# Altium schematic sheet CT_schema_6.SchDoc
size 368 x 245 mm
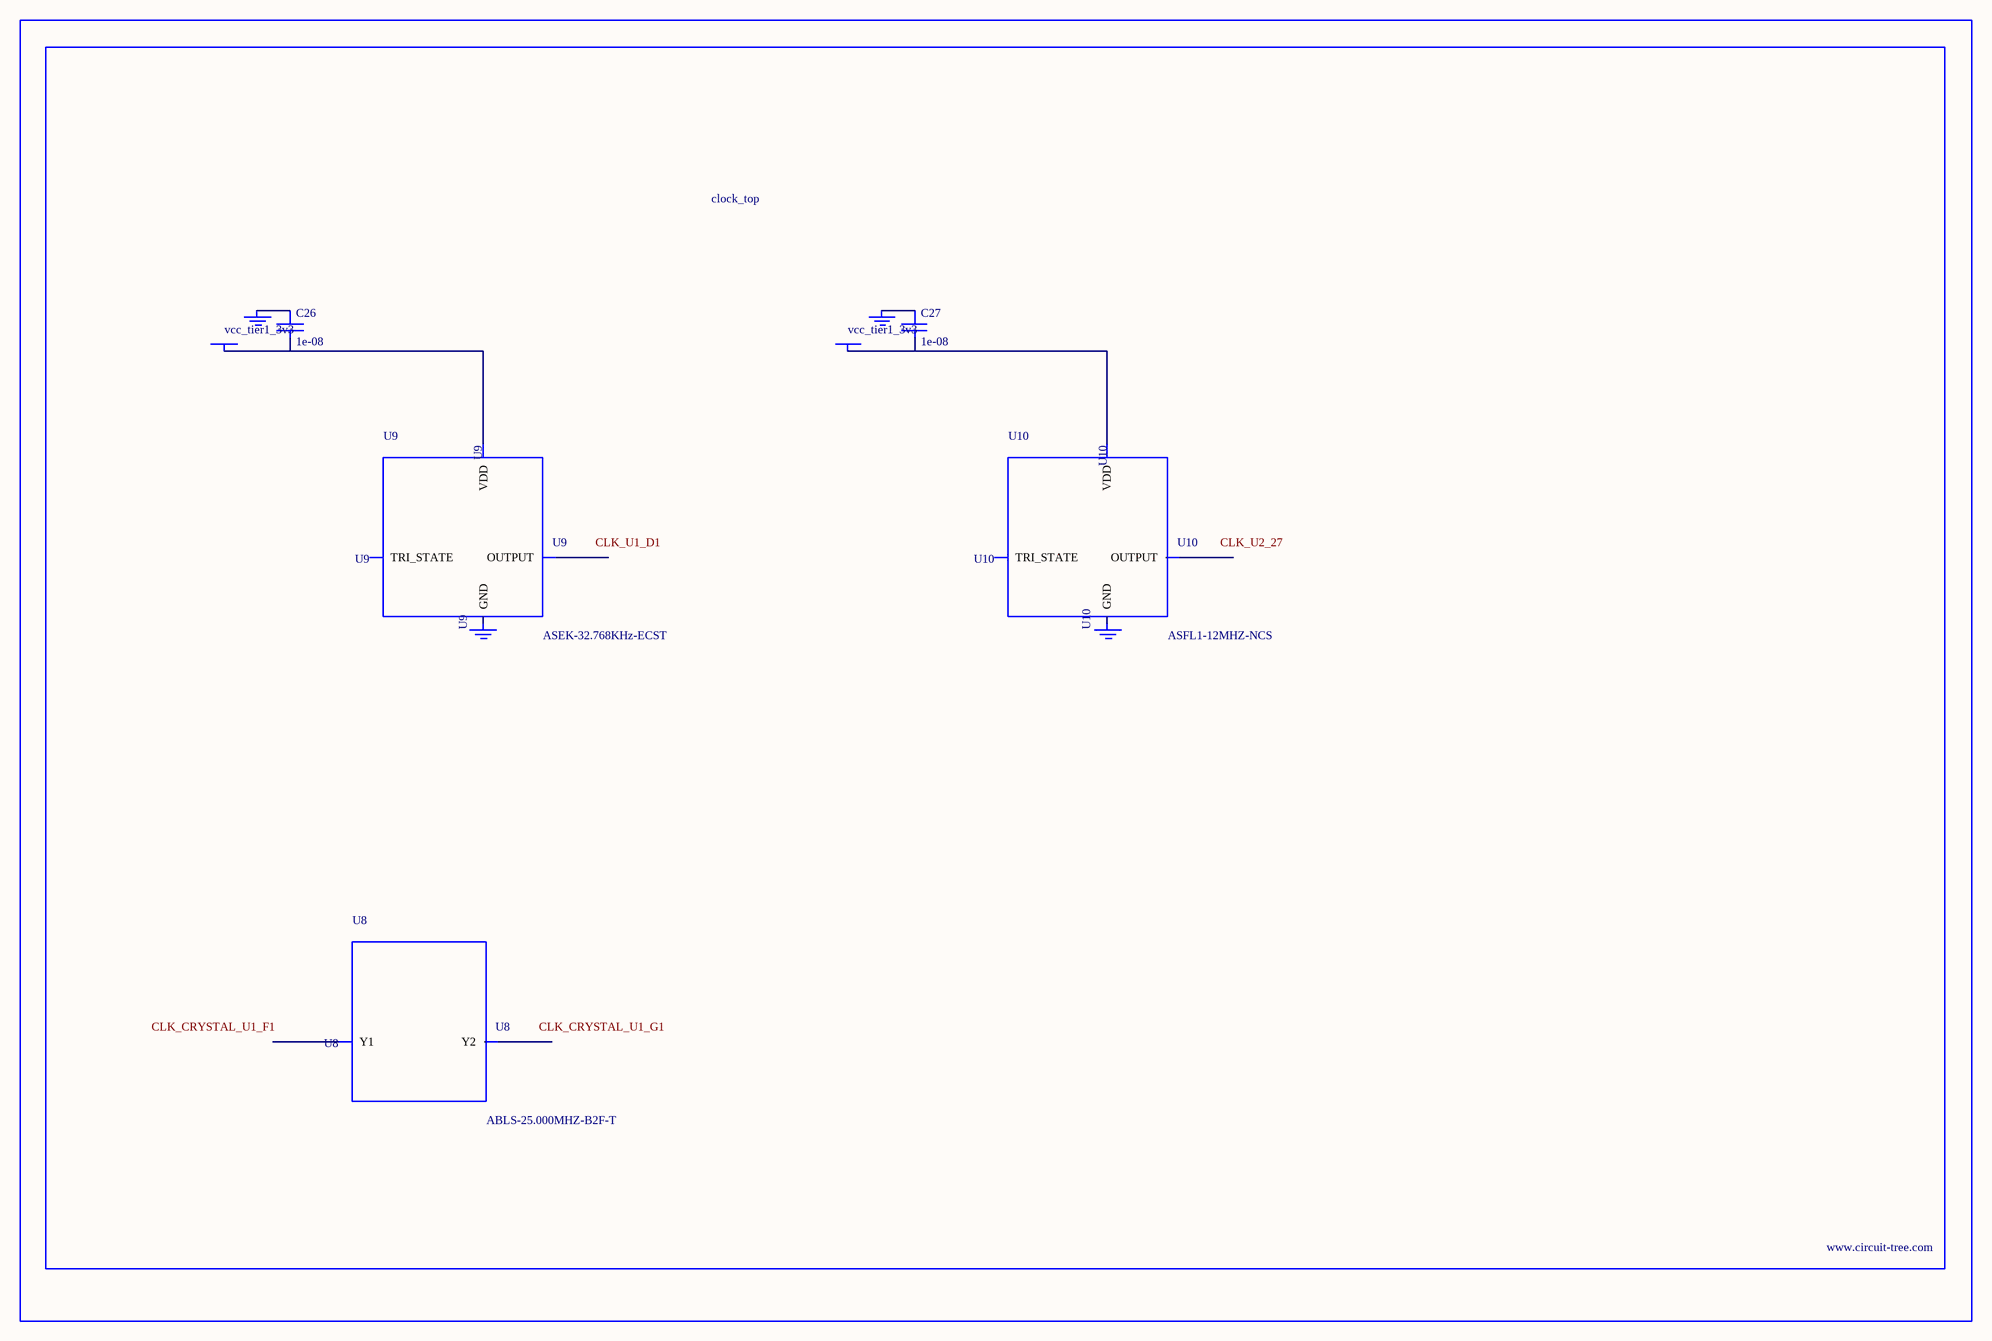
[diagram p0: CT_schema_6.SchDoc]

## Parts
BORDER5  (no value)
C26  1e-08  [C0402]
C27  1e-08  [C0402]
GND_INSTANCE_5_0  (no value)
GND_INSTANCE_5_1  (no value)
GND_INSTANCE_5_2  (no value)
GND_INSTANCE_5_3  (no value)
POWER_INSTANCE_5_0  vcc_tier1_3v3
POWER_INSTANCE_5_1  vcc_tier1_3v3
U8  ABLS-25.000MHZ-B2F-T  [ABLS-25.000MHZ-B2F-T]
U9  ASEK-32.768KHz-ECST  [ASEK]
U10  ASFL1-12MHZ-NCS  [ASFL1]

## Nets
NetC26_1: C26.1 GND_INSTANCE_5_0.0(GND)
NetC26_2: C26.2 POWER_INSTANCE_5_0.0(PWR) U9.4(VDD)
NetC27_1: C27.1 GND_INSTANCE_5_2.0(GND)
NetC27_2: C27.2 POWER_INSTANCE_5_1.0(PWR) U10.4(VDD)

Not connected (* = marked no-connect by the designer): GND_INSTANCE_5_1 0(GND); GND_INSTANCE_5_3 0(GND); U8 1(Y1) 2(Y2); U9 1(TRI_STATE) 2(GND) 3(OUTPUT); U10 1(TRI_STATE) 2(GND) 3(OUTPUT)

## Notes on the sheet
- Labels drawn without touching a wire or pin: CLK_CRYSTAL_U1_F1, CLK_CRYSTAL_U1_G1, CLK_U1_D1, CLK_U2_27

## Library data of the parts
BORDER5 = BORDER_PAGE5
C26 C27 = C0402C103K3RAC
GND_INSTANCE_5_0-GND_INSTANCE_5_3 = GND
POWER_INSTANCE_5_0 POWER_INSTANCE_5_1 = PWR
